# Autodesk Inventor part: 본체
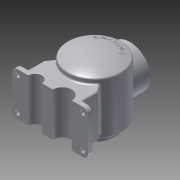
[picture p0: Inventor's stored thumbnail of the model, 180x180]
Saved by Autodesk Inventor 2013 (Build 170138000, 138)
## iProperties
Created: 2018-08
Part Number: 본체
Material: 알루미늄 6061
Document SubType Name: Modeling
Designer: Administrator
Density: 2.71 g/cm^3
Mass: 1886.21 g
Surface Area: 1088.41 cm^2
Volume: 696.02 cm^3
Author: Administrator
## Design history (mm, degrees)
sketch "스케치2"
  geometry: L1 (70, 40)-(-70, 40); L2 (-70, 40)-(-70, -40); L3 (-70, -40)-(70, -40); L4 (70, -40)-(70, 40); L5 (70, 40)-(-70, -40); L6 (-70, 40)-(70, -40); 1 further point
  constraints: 12 end point, 2 midpoint, 2 parallel, 1 horizontal, 1 perpendicular
  dimensions: "d2" = 80 distance between parallel lines of L3 L1; "d4" = 140 distance between parallel lines of L2 L4
extrude "돌출1" new body sketch "스케치2" distance "d5" = 10; taper "d6" = 0 deg
sketch "스케치4"
  geometry: L1 (82, -51.553)-(82, 121.07); L2 (82, -60)-(120, -60); L3 (120, -60)-(120, -48); L4 (120, -48)-(132, -48); L5 (132, -48)-(132, 48.671); L6 (0, -40)-(10, -40) reference; L7 (82, 60)-(82, -60); L8 (109, -60)-(109, -38); L9 (109, -38)-(119, -38); L10 (122, -35)-(122, 40.125); L11 (109, -60)-(120, -60); L12 (82, 60)-(82, 50); A1 r 116 centre (82, -56) between (132, 48.671) and (82, 60); A2 r 106 centre (82, -56) between (120.078, 42.925) and (82, 50); A3 r 3 centre (119, 40.125) between (122, 40.125) and (120.078, 42.925); A4 r 3 centre (119, -35) between (119, -38) and (122, -35); 3 further points
  constraints: 22 end point, 9 point on circle, 7 point on line, 4 centre point, 4 perpendicular, 4 tangent, 3 collinear, 3 parallel, 1 equal radius, 1 vertical
  dimensions: "d22" = 82 distance from line of point (0, 0) L1; "d23" = 50 distance between parallel lines of L5 L1; "d24" = 38 distance between parallel lines of L1 L3; "d27" = 12 distance between parallel lines of L4 L2; "d28" = 8 distance between parallel lines of L4 L6; "d29" = 116 radius of A1; "d30" = 10 radial gap between concentric circles of A1 A2; "d31" = 40 distance between parallel lines of L10 L7; "d32" = 27 distance between parallel lines of L8 L1; "d33" = 22 distance between parallel lines of L9 L2; "d89" = 3 radius of A3; "d104" = 108 vertical distance of L7.start L4.end
revolve "회전1" sketch "스케치4" stored, may be unused: angle "d34" = 90 deg
sketch "스케치3"
  geometry: L1 (70, 10)-(-70, 10) reference; L2 (70, 0)-(70, 10) reference; L3 (50, 38.563)-(50, 10); L4 (-50, 10)-(-50, 38.563); L5 (-70, 0)-(-70, 10) reference; L6 (-70, 10)-(-70, 80.948); L7 (70, 10)-(70, 68.048); L8 (-70, 10)-(-10.973, 94.3); L9 (70, 10)-(9.248, 96.763); L10 (-50, 38.563)-(-38.767, 54.606); L11 (50, 38.563)-(38.767, 54.606); L12 (-38.767, 54.606)-(-10.767, 35); L13 (-10.767, 35)-(10.767, 35); L14 (10.767, 35)-(38.767, 54.606); 1 further point
  constraints: 22 end point, 6 point on line, 4 perpendicular, 3 collinear, 2 parallel, 1 equal length
  dimensions: "d14" = 20 distance between parallel lines of L5 L4; "d15" = 20 distance between parallel lines of L2 L3; "d19" = 35 deg angle of L8 L6; "d20" = 35 deg angle of L7 L9; "d35" = 35 distance from line of L13 point (0, 0); "d36" = 28 horizontal distance of L10.end L12.end
extrude "돌출2" join sketch "스케치3" stored distance "d37" = 80; taper "d38" = 0 deg
fillet "모깎기1" dims "d39" = 10
sketch "스케치5"
  geometry: L1 (50, 40)-(50, -40) reference; L2 (50, -40)-(60, -40) reference; L3 (70, -30)-(70, 30) reference; L4 (60, 40)-(50, 40) reference; C1 r 4 at (60, 30); C2 r 4 at (60, -30); C3 r 4 at (-60, 30); C4 r 4 at (-60, -30); A1 r 10 centre (60, 30) between (70, 30) and (60, 40) reference; A2 r 10 centre (60, -30) between (60, -40) and (70, -30) reference; A3 r 10 centre (-60, 30) between (-60, 40) and (-70, 30) reference; A4 r 10 centre (-60, -30) between (-70, -30) and (-60, -40) reference; 1 further point
  constraints: 4 centre point, 4 coincident
  dimensions: "d40" = 8 diameter of C1; "d42" = 8 diameter of C2; "d43" = 8 diameter of C3; "d44" = 8 diameter of C4
extrude "돌출3" cut sketch "스케치5" distance "d45" = 10; taper "d46" = 0 deg
sketch "스케치6"
  geometry: L1 (-60, -82)-(60, -82) reference; C1 r 12.5 at (-27.5, -82); C2 r 17.5 at (22.5, -82); 1 further point
  constraints: 2 centre point, 2 point on line
  dimensions: "d50" = 27.5 distance of point (0, -82) C1.centre; "d51" = 22.5 distance of C2.centre point (0, -82); "d52" = 12.5 radius of C1; "d53" = 35 diameter of C2
extrude "돌출4" cut sketch "스케치6" distance "d54" = 90; taper "d55" = 0 deg
node "작업 평면1"
sketch "스케치7"
  geometry: L1 (-38, -60)-(38, -60) reference; L2 (0, 0)-(0, 80.618); C1 r 38 at (0, 2)
  constraints: 2 end point, 1 centre point, 1 perpendicular, 1 point on line
  dimensions: "d57" = 62 distance from line of L1 C1.centre; "d58" = 76 diameter of C1
extrude "돌출5" join sketch "스케치7" stored distance "d59" = 90; taper "d60" = 0 deg
sketch "스케치8"
  geometry: C1 r 38 at (0, 0) reference; C2 r 27 at (0, 0); 1 further point
  constraints: 1 centre point, 1 concentric
  dimensions: "d61" = 54 diameter of C2
extrude "돌출6" cut sketch "스케치8" stored distance "d63" = 90; taper "d64" = 0 deg
sketch "스케치9" dims "d65" = 65
  geometry: L1 (0, 2)-(0, 69.763); C1 r 38 at (0, 0) reference; 2 further points
  constraints: 2 end point, 1 point on line, 1 vertical, 1 vertical alignment, 3 other
hole "구멍1" sketch "스케치9" at (0, 32.5) diameter "d67" = 3.242; stored, may be unused: countersink angle "d71" = 90 deg, drill point angle "d73" = 118 deg; dims "d68" = 8, "d69" = 4, "d70" = 2, "d72" = 10
sketch "스케치10" dims "d77" = 65
  geometry: L1 (0, -82)-(0, 53.947); C1 r 38 at (0, 0) reference; 2 further points
  constraints: 2 end point, 1 point on line, 1 vertical, 1 vertical alignment, 3 other
hole "구멍2" sketch "스케치10" at (0, 32.5) diameter "d79" = 3.242; stored, may be unused: countersink angle "d83" = 90 deg, drill point angle "d85" = 118 deg; dims "d80" = 8, "d81" = 4, "d82" = 2, "d84" = 10
fillet "모깎기2" dims "d90" = 3
fillet "모깎기3" dims "d91" = 3
fillet "모깎기4" dims "d92" = 3
fillet "모깎기5" dims "d93" = 3
node "작업 평면2"
sketch "스케치11" dims "d95" = 65
  geometry: C1 r 50 at (60, 82) reference; A1 r 32.5 centre (60, 82) between (92.5, 82) and (27.5, 82); 2 further points
  constraints: 2 point on circle, 1 centre point, 1 coincident, 1 horizontal alignment, 5 other
feature "엠보싱1" sketch "스케치11" dims "d2" = 80, "d4" = 140, "d22" = 82, "d97" = 0.5, "d98" = 0
fillet "모깎기6" dims "d99" = 3
chamfer "모따기1" distance "d100" = 1; stored, may be unused: second distance "d101" = 2, angle "d102" = 45 deg
fillet "모깎기7" dims "d105" = 3
node "솔리드1"
pattern_circular "원형 패턴1" dims angle "d75" = 360 deg
pattern_circular "원형 패턴2" dims angle "d87" = 360 deg
node "투영된 루프1"
other parameters: "d56" = 147, "d94" = 18
